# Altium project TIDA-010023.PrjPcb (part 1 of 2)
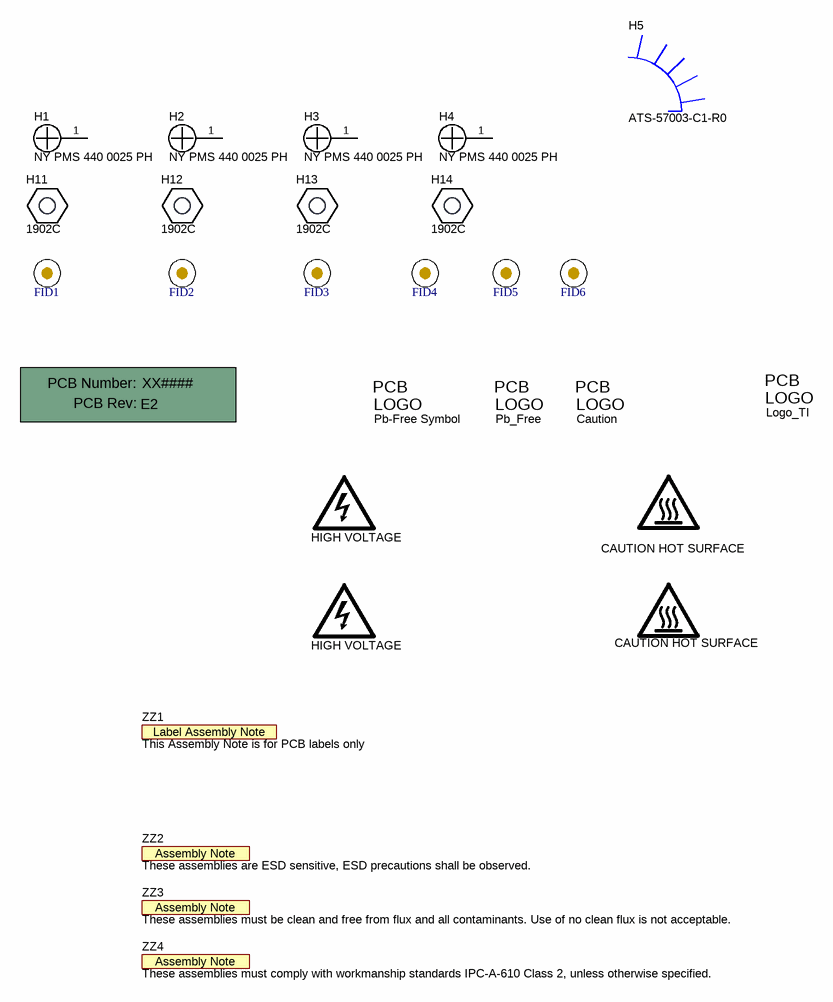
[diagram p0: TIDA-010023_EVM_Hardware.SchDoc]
CopyrightYear: 2017; PCB_Layout: Who did the Layout?; PCB_Rev: E1; PRJ_Customer: Public Release; PRJ_Engineer: Enter name of project lead; PRJ_Number: XX####; PRJ_Title: Change in menu Project|Project Options|Parameters; SCH_Rev: E1; TechSupport: http://www.ti.com/support; TID: N/A
5 sheets, 264 parts. Net scope: flat (ports and power ports of the same name join across sheets).
Board file: TIDA-010023_PCB.PcbDoc
Sheets:
  TIDA-010023_EVM_Hardware.SchDoc
  TIDA-010023_Current_Sensing.SchDoc
  TIDA-010023_Inverter.SchDoc
  TIDA-010023_MCU.SchDoc
  TIDA-010023_CoverSheet.SchDoc

## Sheet TIDA-010023_EVM_Hardware.SchDoc
size 431 x 279 mm; Date: Not shown in title block; ApprovedBy: Not shown in title block; CheckedBy: Not shown in title block; Author: Not shown in title block; CompanyName: Not shown in title block; Engineer: Not shown in title block; Organization: Not shown in title block; Address1: Not shown in title block; Address2: Not shown in title block; Address3: Not shown in title block; Address4: Not shown in title block; DocumentNumber: 1; Revision: Use project parameter SCH_Rev; SheetNumber: 3; SheetTotal: 3; PageSetup: Record=PageOptions¦CenterHorizontal=True¦CenterVertical=True¦PrintScale=1.00¦XCorrection=1.00¦YCorrection=1.00¦PrintKind=0¦BorderSize=5000000¦LeftOffset=0¦BottomOffset=0¦Orientation=2¦PaperLength=1000¦PaperWidth=1000¦Scale=100¦PaperSource=15¦PrintQuality=600¦MediaType=1¦DitherType=10¦PaperKind=Letter¦PrintScaleMode=1

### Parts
3  CAUTION HOT SURFACE  [IEC_HotSurface_small]  (no BOM)
4  CAUTION HOT SURFACE  [IEC_HotSurface_small]  (no BOM)
5  HIGH VOLTAGE  [IEC_HighVoltage_small]  (no BOM)
6  HIGH VOLTAGE  [IEC_HighVoltage_small]  (no BOM)
Caution  CAUTION.  READ USER GUIDE BEFORE USE  [IEC_Caution_small]  (value not drawn)  (no BOM)
FID1  Fiducial  [Fiducial10-30]  (value not drawn)
FID2  Fiducial  [Fiducial10-30]  (value not drawn)
FID3  Fiducial  [Fiducial10-30]  (value not drawn)
FID4  Fiducial  [Fiducial10-30]  (value not drawn)
FID5  Fiducial  [Fiducial10-30]  (value not drawn)
FID6  Fiducial  [Fiducial10-30]  (value not drawn)
H1  NY PMS 440 0025 PH  [NY PMS 440 0025 PH]
H2  NY PMS 440 0025 PH  [NY PMS 440 0025 PH]
H3  NY PMS 440 0025 PH  [NY PMS 440 0025 PH]
H4  NY PMS 440 0025 PH  [NY PMS 440 0025 PH]
H5  ATS-57003-C1-R0  [FE_LAM_5_K_100]  (mechanical)
H11  1902C  [Keystone_1902C]
H12  1902C  [Keystone_1902C]
H13  1902C  [Keystone_1902C]
H14  1902C  [Keystone_1902C]
LBL1  Printed Circuit Board  [Label_650x200]  (value not drawn)  (mechanical)
Logo_TI  Texas Instruments  [TI_Horizontal_Overlay_Small]  (value not drawn)  (no BOM)
Pb  Pb-Free Symbol  [Pb-Free_Overlay_Small]  (no BOM)
Pb_Free  ESD Susceptible  [ESD_Overlay_small]  (value not drawn)  (no BOM)
ZZ1  This Assembly Note is for PCB labels only  [AssemblyNoteLabel]  (no BOM)
ZZ2  These assemblies are ESD sensitive, ESD precautions shall be observed.  [AssemblyNote]  (no BOM)
ZZ3  These assemblies must be clean and free from flux and all contaminants. Use of no clean flux is not acceptable.  [AssemblyNote]  (no BOM)
ZZ4  These assemblies must comply with workmanship standards IPC-A-610 Class 2, unless otherwise specified.  [AssemblyNote]  (no BOM)

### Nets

Not connected (* = marked no-connect by the designer): H1 1; H2 1; H3 1; H4 1

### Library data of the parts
3 4 = IEC_HotSurface: IEC 61010-1 Hot Surface Warning; SymbolCreator: a0412235
5 6 = IEC_HighVoltage: IEC 61010-1 High Voltage Warning; SymbolCreator: a0412235
Caution = IEC_Caution: IEC 61010-1 Caution Warning; SymbolCreator: a0412235
FID1-FID6 = Fiducial: Fiducial mark.  There is nothing to buy or mount.; SymbolCreator: codlsc
H1-H4 = NY PMS 440 0025 PH: Machine Screw, Round, #4-40 x 1/4, Nylon, Philips panhead; Manufacturer: B&F Fastener Supply; CompType: Hardware; SymbolCreator: codlsc; U/M: EA
H5 = LAM 5 K 100: HEAT SINK 94MM X 94MM X 27MM; Manufacturer: Advanced Thermal Solutions Inc.; SymbolCreator: a0412235
H11-H14 = 1902C: Standoff, Hex, 0.5"L #4-40 Nylon; Manufacturer: Keystone; CompType: Hardware
LBL1 = PCB: Manufacturer: Any; PartNumber: XX####; SymbolCreator: a0412235
Logo_TI = TI_Logo: Texas Instrument Corporate Signature; SymbolCreator: a0412235
Pb = Pb-Free: SymbolCreator: a0412235
Pb_Free = ESD_Susceptible: ESD Susceptible Symbol; SymbolCreator: a0412235
ZZ1 = AssemblyNoteLabel: SymbolCreator: a0412235
ZZ2-ZZ4 = AssemblyNote: SymbolCreator: codlsc

## Sheet TIDA-010023_Current_Sensing.SchDoc
size 431 x 279 mm; Date: Not shown in title block; ApprovedBy: Not shown in title block; CheckedBy: Not shown in title block; Author: Not shown in title block; CompanyName: Not shown in title block; Engineer: Not shown in title block; Organization: Not shown in title block; Address1: Not shown in title block; Address2: Not shown in title block; Address3: Not shown in title block; Address4: Not shown in title block; DocumentNumber: 1; Revision: Use project parameter SCH_Rev; SheetNumber: 2; SheetTotal: 3; PageSetup: Record=PageOptions¦CenterHorizontal=True¦CenterVertical=True¦PrintScale=1.00¦XCorrection=1.00¦YCorrection=1.00¦PrintKind=0¦BorderSize=5000000¦LeftOffset=0¦BottomOffset=0¦Orientation=2¦PaperLength=1000¦PaperWidth=1000¦Scale=100¦PaperSource=15¦PrintQuality=600¦MediaType=1¦DitherType=10¦PaperKind=Letter¦PrintScaleMode=1
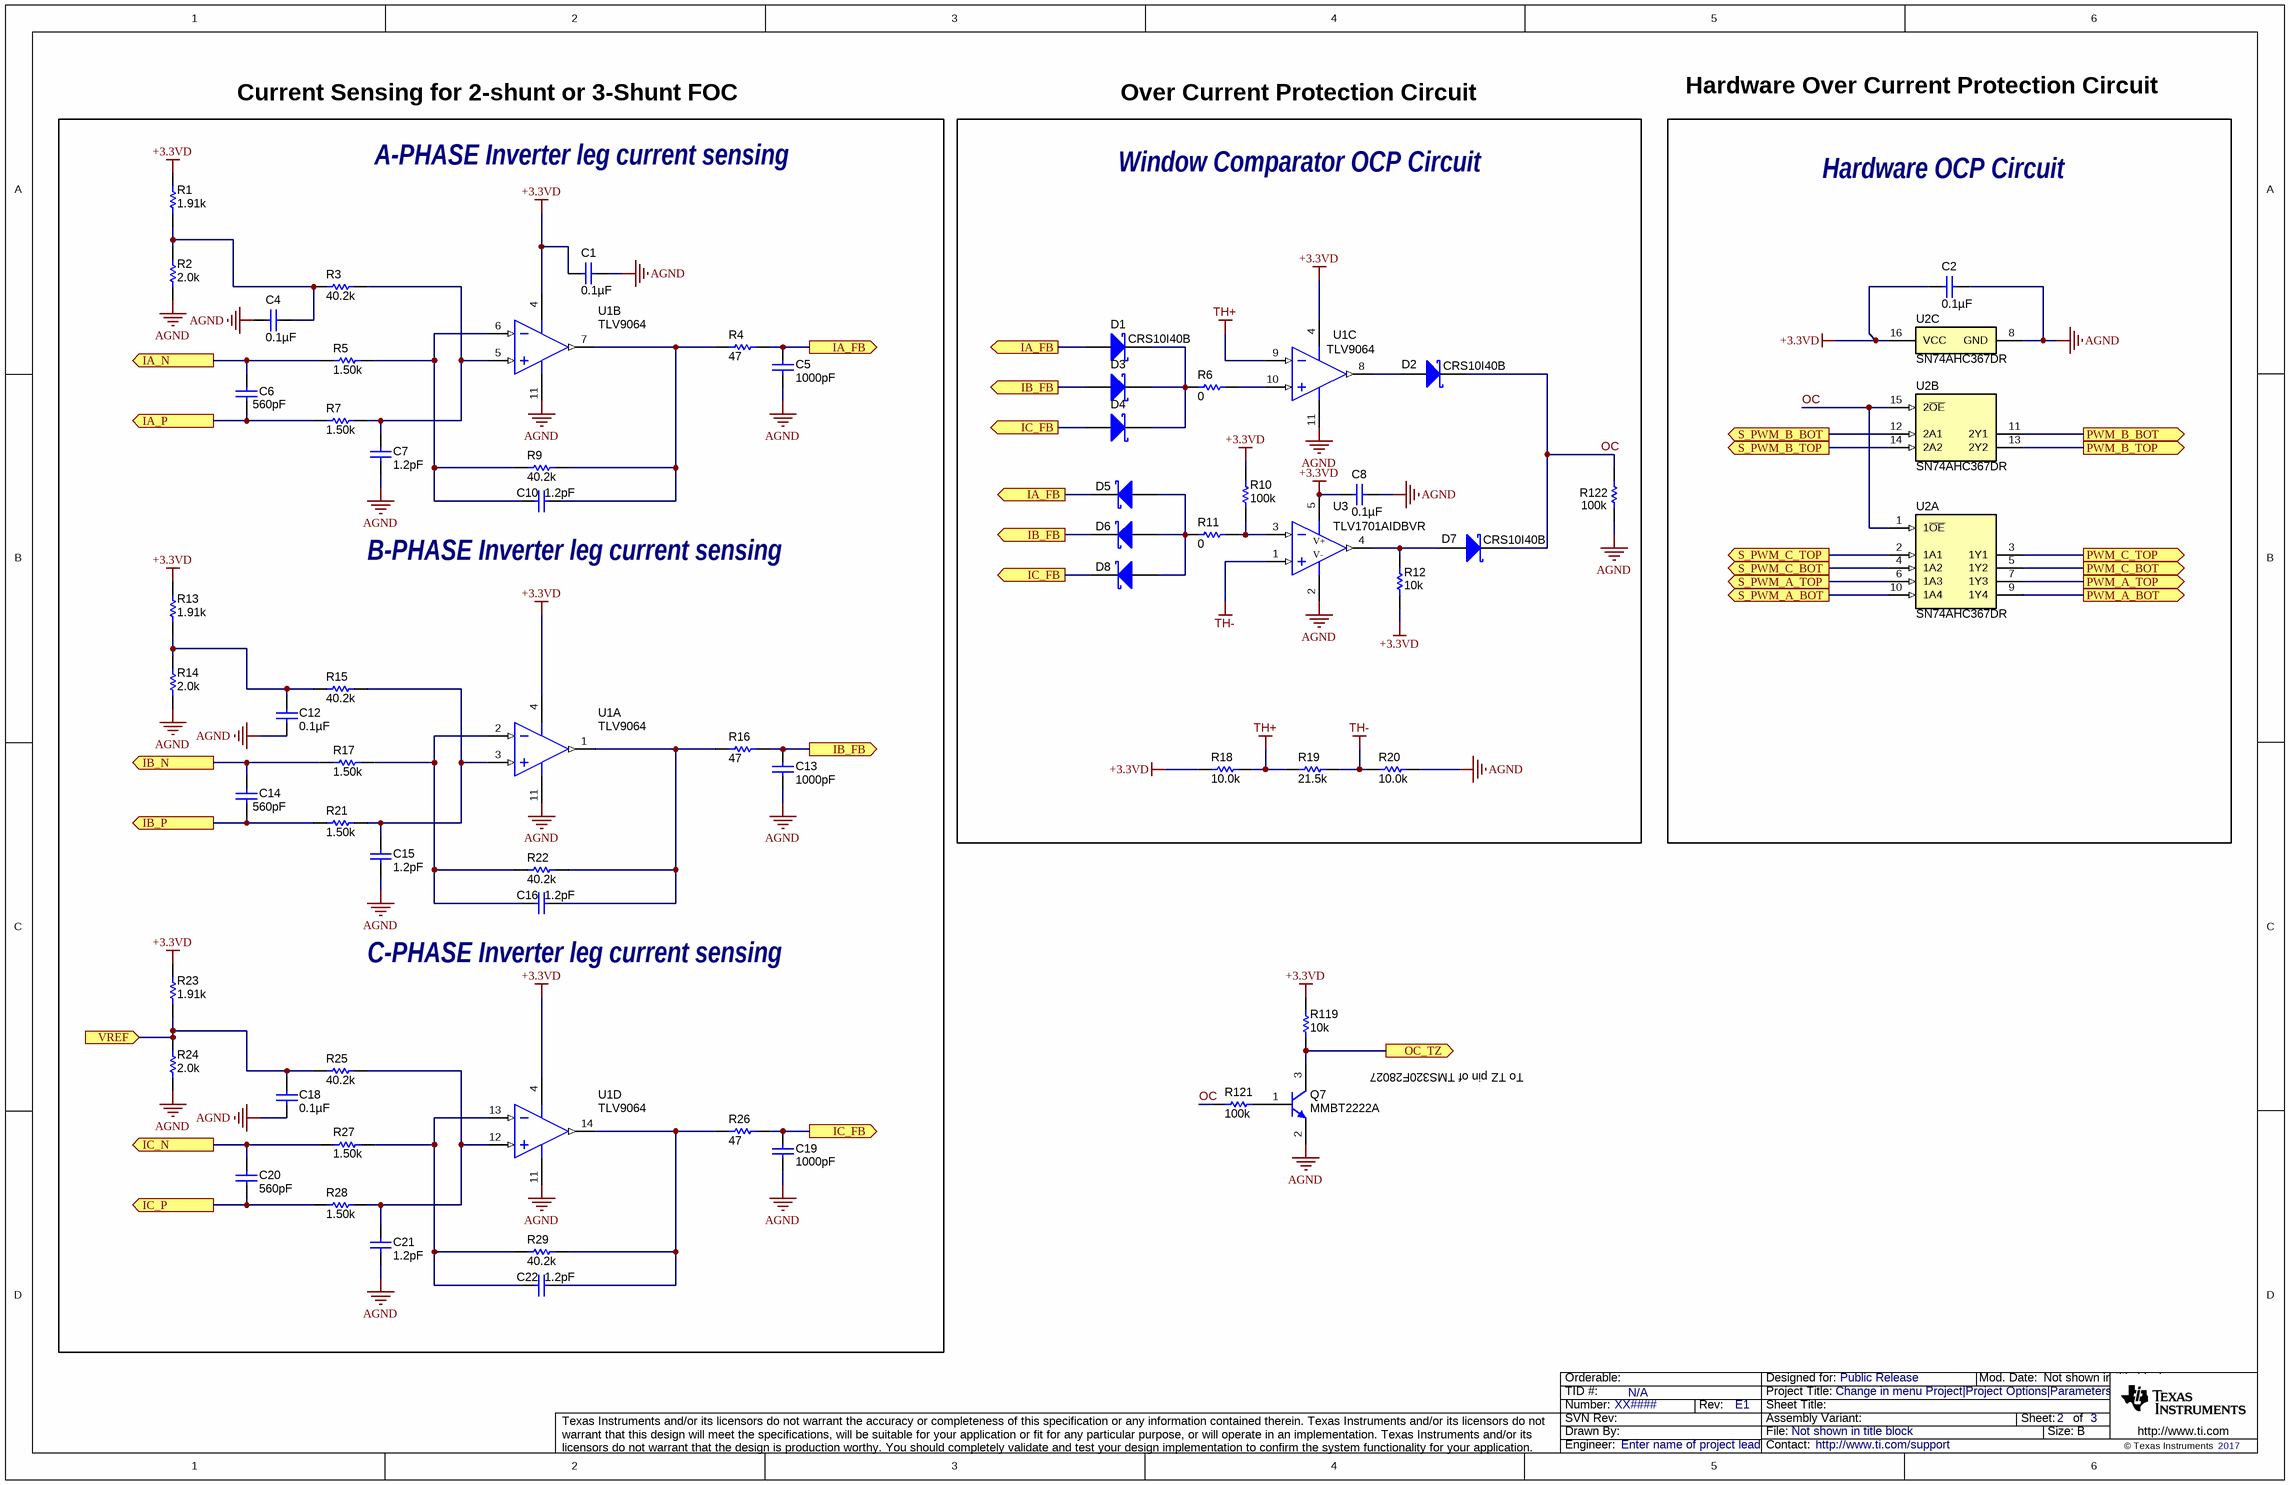
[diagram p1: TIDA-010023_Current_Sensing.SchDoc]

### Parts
C1  ValueDisplayed: 0.1µF  [0603]  (hidden comment: 0603YC104JAT2A)
C2  ValueDisplayed: 0.1µF  [0603]  (hidden comment: 0603YC104JAT2A)
C4  ValueDisplayed: 0.1µF  [0603]  (hidden comment: 0603YC104JAT2A)
C5  ValueDisplayed: 1000pF  [0603]  (hidden comment: 0603ZC102KAT2A)
C6  ValueDisplayed: 560pF  [0603]  (hidden comment: GRM1885C1E561JA01D)
C7  ValueDisplayed: 1.2pF  [0603]  (hidden comment: CL10C1R2BB8NNNC)
C8  ValueDisplayed: 0.1µF  [0603]  (hidden comment: 0603YC104JAT2A)
C10  ValueDisplayed: 1.2pF  [0603]  (hidden comment: CL10C1R2BB8NNNC)
C12  ValueDisplayed: 0.1µF  [0603]  (hidden comment: 0603YC104JAT2A)
C13  ValueDisplayed: 1000pF  [0603]  (hidden comment: 06035A221FAT2A)
C14  ValueDisplayed: 560pF  [0603]  (hidden comment: GRM1885C1E561JA01D)
C15  ValueDisplayed: 1.2pF  [0603]  (hidden comment: CL10C1R2BB8NNNC)
C16  ValueDisplayed: 1.2pF  [0603]  (hidden comment: CL10C1R2BB8NNNC)
C18  ValueDisplayed: 0.1µF  [0603]  (hidden comment: 0603YC104JAT2A)
C19  ValueDisplayed: 1000pF  [0603]  (hidden comment: 06035A221FAT2A)
C20  ValueDisplayed: 560pF  [0603]  (hidden comment: GRM1885C1E561JA01D)
C21  ValueDisplayed: 1.2pF  [0603]  (hidden comment: CL10C1R2BB8NNNC)
C22  ValueDisplayed: 1.2pF  [0603]  (hidden comment: CL10C1R2BB8NNNC)
D1  CRS10I40B  [SOD-123]
D2  CRS10I40B  [SOD-123]
D3  1N5819HW-7-F  [SOD-123]  (value not drawn)
D4  1N5819HW-7-F  [SOD-123]  (value not drawn)
D5  1N5819HW-7-F  [SOD-123]  (value not drawn)
D6  1N5819HW-7-F  [SOD-123]  (value not drawn)
D7  CRS10I40B  [SOD-123]
D8  1N5819HW-7-F  [SOD-123]  (value not drawn)
Q7  MMBT2222A  [SOT-23]
R1  ValueDisplayed: 1.91k  [0603]  (hidden comment: CRCW06031K91FKEA)
R2  ValueDisplayed: 2.0k  [0603]  (hidden comment: CRCW06032K00JNEA)
R3  ValueDisplayed: 40.2k  [0603]  (hidden comment: CRCW060340K2FKEA)
R4  ValueDisplayed: 47  [0603]  (hidden comment: CRCW060347R0JNEA)
R5  ValueDisplayed: 1.50k  [0603]  (hidden comment: CRCW06031K50FKEA)
R6  ValueDisplayed: 0  [0603]  (hidden comment: MCR03EZPJ000)
R7  ValueDisplayed: 1.50k  [0603]  (hidden comment: CRCW06031K50FKEA)
R9  ValueDisplayed: 40.2k  [0603]  (hidden comment: CRCW060340K2FKEA)
R10  ValueDisplayed: 100k  [0603]  (hidden comment: CRCW0603100KJNEA)
R11  ValueDisplayed: 0  [0603]  (hidden comment: MCR03EZPJ000)
R12  ValueDisplayed: 10k  [0603]  (hidden comment: CRCW060310K0JNEA)
R13  ValueDisplayed: 1.91k  [0603]  (hidden comment: CRCW06031K91FKEA)
R14  ValueDisplayed: 2.0k  [0603]  (hidden comment: CRCW06032K00JNEA)
R15  ValueDisplayed: 40.2k  [0603]  (hidden comment: CRCW060340K2FKEA)
R16  ValueDisplayed: 47  [0603]  (hidden comment: CRCW060347R0JNEA)
R17  ValueDisplayed: 1.50k  [0603]  (hidden comment: CRCW06031K50FKEA)
R18  ValueDisplayed: 10.0k  [0603]  (hidden comment: CRCW060310K0FKEA)
R19  ValueDisplayed: 21.5k  [0603]  (hidden comment: CRCW060321K5FKEA)
R20  ValueDisplayed: 10.0k  [0603]  (hidden comment: CRCW060310K0FKEA)
R21  ValueDisplayed: 1.50k  [0603]  (hidden comment: CRCW06031K50FKEA)
R22  ValueDisplayed: 40.2k  [0603]  (hidden comment: CRCW060340K2FKEA)
R23  ValueDisplayed: 1.91k  [0603]  (hidden comment: CRCW06031K91FKEA)
R24  ValueDisplayed: 2.0k  [0603]  (hidden comment: CRCW06032K00JNEA)
R25  ValueDisplayed: 40.2k  [0603]  (hidden comment: CRCW060340K2FKEA)
R26  ValueDisplayed: 47  [0603]  (hidden comment: CRCW060347R0JNEA)
R27  ValueDisplayed: 1.50k  [0603]  (hidden comment: CRCW06031K50FKEA)
R28  ValueDisplayed: 1.50k  [0603]  (hidden comment: CRCW06031K50FKEA)
R29  ValueDisplayed: 40.2k  [0603]  (hidden comment: CRCW060340K2FKEA)
R119  ValueDisplayed: 10k  [0603]  (hidden comment: CRCW060310K0JNEA)
R121  ValueDisplayed: 100k  [0603]  (hidden comment: CRCW0603100KJNEA)
R122  ValueDisplayed: 100k  [0603]  (hidden comment: CRCW0603100KJNEA)
U1  TLV9064  [tssop-14]  (parts A,B,C,D of 4)
U2  SN74AHC367DR  [D0016A_N]  (parts A,B,C of 3)
U3  TLV1701AIDBVR  [DBV0005A_N]

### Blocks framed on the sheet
Window Comparator OCP Circuit: C8 D1-D8 R6 R10-R12 R18-R20 R122 U1 U3
Hardware OCP Circuit: C2 U2

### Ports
IA_FB (out), IA_N (out), IA_P (out), IB_FB (out), IB_N (out), IB_P (out), IC_FB (out), IC_N (out), IC_P (out), OC_TZ (out), PWM_A_BOT (out), PWM_A_TOP (out), PWM_B_BOT (out), PWM_B_TOP (out), PWM_C_BOT (out), PWM_C_TOP (out), S_PWM_A_BOT (out), S_PWM_A_TOP (out), S_PWM_B_BOT (out), S_PWM_B_TOP (out), S_PWM_C_BOT (out), S_PWM_C_TOP (out), VREF (in)

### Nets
+3.3VD: C1.1 C2.2 C8.1 R1.2 R10.1 R12.2 R13.2 R18.2 R23.2 R119.1 U1.4(VDD) U2.16(VCC) U3.5(V+)
AGND: C1.2 C2.1 C4.1 C5.2 C7.2 C8.2 C12.2 C13.2 C15.2 C18.2 C19.2 C21.2 Q7.2(E) R2.1 R14.1 R20.1 R24.1 R122.1 U1.11(GND) U2.8(GND) U3.2(V-)
TH+: R18.1 R19.2 U1.9(IN3-)
TH-: R19.1 R20.2 U3.1(IN+)
IA_FB: C5.1 D1.2(A) D5.1(K) R4.2 ; port IA_FB
IA_N: C6.1 R5.1 ; port IA_N
IA_P: C6.2 R7.1 ; port IA_P
IB_FB: C13.1 D3.2(A) D6.1(K) R16.2 ; port IB_FB
IB_N: C14.1 R17.1 ; port IB_N
IB_P: C14.2 R21.1 ; port IB_P
IC_FB: C19.1 D4.2(A) D8.1(K) R26.2 ; port IC_FB
IC_N: C20.2 R27.1 ; port IC_N
IC_P: C20.1 R28.1 ; port IC_P
OC: D2.1(K) D7.1(K) R121.1 R122.2 U2.1(1~{OE}) U2.15(2~{OE})
OC_TZ: Q7.3(C) R119.2 ; port OC_TZ
PWM_A_BOT: U2.9(1Y4) ; port PWM_A_BOT
PWM_A_TOP: U2.7(1Y3) ; port PWM_A_TOP
PWM_B_BOT: U2.11(2Y1) ; port PWM_B_BOT
PWM_B_TOP: U2.13(2Y2) ; port PWM_B_TOP
PWM_C_BOT: U2.5(1Y2) ; port PWM_C_BOT
PWM_C_TOP: U2.3(1Y1) ; port PWM_C_TOP
S_PWM_A_BOT: U2.10(1A4) ; port S_PWM_A_BOT
S_PWM_A_TOP: U2.6(1A3) ; port S_PWM_A_TOP
S_PWM_B_BOT: U2.12(2A1) ; port S_PWM_B_BOT
S_PWM_B_TOP: U2.14(2A2) ; port S_PWM_B_TOP
S_PWM_C_BOT: U2.4(1A2) ; port S_PWM_C_BOT
S_PWM_C_TOP: U2.2(1A1) ; port S_PWM_C_TOP
VREF: C18.1 R23.1 R24.2 R25.1 ; port VREF
NetC4_2: C4.2 R1.1 R2.2 R3.1
NetC7_1: C7.1 R3.2 R7.2 U1.5(IN2+)
NetC10_1: C10.1 R4.1 R9.2 U1.7(OUT2)
NetC10_2: C10.2 R5.2 R9.1 U1.6(IN2-)
NetC12_1: C12.1 R13.1 R14.2 R15.1
NetC15_1: C15.1 R15.2 R21.2 U1.3(IN1+)
NetC16_1: C16.1 R16.1 R22.2 U1.1(OUT1)
NetC16_2: C16.2 R17.2 R22.1 U1.2(IN1-)
NetC21_1: C21.1 R25.2 R28.2 U1.12(IN4+)
NetC22_1: C22.1 R26.1 R29.2 U1.14(OUT4)
NetC22_2: C22.2 R27.2 R29.1 U1.13(IN4-)
NetD1_1: D1.1(K) D3.1(K) D4.1(K) R6.2
NetD2_2: D2.2(A) U1.8(OUT3)
NetD5_2: D5.2(A) D6.2(A) D8.2(A) R11.2
NetD7_2: D7.2(A) R12.1 U3.4(OUT)
NetQ7_1: Q7.1(B) R121.2
NetR6_1: R6.1 U1.10(IN3+)
NetR10_2: R10.2 R11.1 U3.3(IN-)

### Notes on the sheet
- Current Sensing for 2-shunt or 3-Shunt FOC
- Over Current Protection Circuit
- Hardware Over Current Protection Circuit
- A-PHASE Inverter leg current sensing
- (near C10) B-PHASE Inverter leg current sensing
- (near C16) C-PHASE Inverter leg current sensing
- To TZ pin of TMS320F28027

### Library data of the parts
C1 C4 C12 C18 = 0603YC104JAT2A: CAP, CERM, 0.1 µF, 16 V, +/- 5%, X7R, 0603; Manufacturer: AVX; Polarized: N; CompType: Capacitor; Value: 0.1uF; U/M: EA; Cap_F: 0.0000001; Tolerance_%: 5; ESR_ohm: 0.039; Value1: 0.039 ohm; VDC_V: 16; Value2: 16V; TaMin_C: -55; TaMax_C: 125; SizeArea_mm2: 1.28; SizeAreaWB_mm2: 4.68; SizeX_mm: 1.6; SizeY_mm: 0.8; SizeZ_mm: 1; AEC Category: Q200
C2 C8 = 0603YC104JAT2A: CAP, CERM, 0.1 µF, 16 V, +/- 5%, X7R, 0603; Manufacturer: AVX; Polarized: N; CompType: Capacitor; Value: 0.1uF; U/M: EA; Cap_F: 0.0000001; Tolerance_%: 5; ESR_ohm: 0.039; Value1: 0.039 ohm; VDC_V: 16; Value2: 16V; TaMin_C: -55; TaMax_C: 125
C5 = 0603ZC102KAT2A: CAP, CERM, 1000 pF, 10 V,+/- 10%, X7R, 0603; Manufacturer: AVX; Polarized: N; CompType: Capacitor; Value: 1000pF; U/M: EA; Cap_F: 0.000000001; Tolerance_%: 10; Value2: 10V; TaMin_C: -55; TaMax_C: 125; SizeArea_mm2: 1.28; SizeAreaWB_mm2: 4.68; SizeX_mm: 1.6; SizeY_mm: 0.8; SizeZ_mm: 1; AEC Category: Q200
C6 C14 C20 = GRM1885C1E561JA01D: CAP, CERM, 560 pF, 25 V,+/- 5%, C0G/NP0, 0603; Manufacturer: MuRata; Polarized: N; CompType: Capacitor; Value: 560pF; U/M: EA; Cap_F: 0.00000000056; Tolerance_%: 5; VDC_V: 25; Value2: 25V; TaMin_C: -55; TaMax_C: 125; SizeArea_mm2: 1.28; SizeAreaWB_mm2: 4.68; SizeX_mm: 1.6; SizeY_mm: 0.8; SizeZ_mm: 1; AEC Category: Q200
C7 C10 C15 C16 C21 C22 = CL10C1R2BB8NNNC: CAP, CERM, 1.2 pF, 50 V,+/- 10%, C0G/NP0, 0603; Manufacturer: Samsung Electro-Mechanics; Polarized: N; CompType: Capacitor; Value: 1.2pF; U/M: EA; Cap_F: 0.0000000000012; Tolerance_%: 10; VDC_V: 50; Value2: 50V; TaMin_C: -55; TaMax_C: 125; SizeArea_mm2: 1.28; SizeAreaWB_mm2: 4.68; SizeX_mm: 1.6; SizeY_mm: 0.8; SizeZ_mm: 1; AEC Category: Q200
C13 C19 = 06035A221FAT2A: CAP, CERM, 220 pF, 50 V, +/- 1%, C0G/NP0, 0603; Manufacturer: AVX; Polarized: N; CompType: Capacitor; Value: 220pF; U/M: EA; Cap_F: 0.00000000022; Tolerance_%: 1; ESR_ohm: 0.083; Value1: 0.083 ohm; VDC_V: 50; Value2: 50V; TaMin_C: -55; TaMax_C: 125
D1-D8 = 1N5819HW-7-F: Diode, Schottky, 40V, 1A, SOD-123; Manufacturer: Diodes Inc.; U/M: EA; Vf_V: 0.45; Value2: 0.45V; Io_A: 1; Vr_V: 40; TJmax_C: 125
Q7 = MMBT2222A, Fairchild Semiconductor: Transistor, NPN, 40 V, 0.15 A, SOT-23; CompType: BJT; PNP: 0; NPN: 1; Vceo_V: 40; Vcesat1_V: 0.3; Value: 40 V; IcRated_A: 0.15; Value1: 0.15 A; HfeMax: 300; TaMin_C: -55; TaMax_C: 150; SizeAreaWB_mm2: 14; SizeArea_mm2: 7.5; SizeX_mm: 2.5; SizeY_mm: 3; SizeZ_mm: 1.1; U/M: EA; AEC Category: Q101; Green_Lifecycle: Active; Green_REACh: Passed
R1 R13 R23 = CRCW06031K91FKEA: RES, 1.91 k, 1%, 0.1 W, 0603; Manufacturer: Vishay-Dale; CompType: Resistor; Value: 1.91k; Res_ohm: 1910; Value_Code: 1k91; Tolerance_%: 1; Power_W: 0.1; Value2: 0.1W; VDC_V: 75; TempCo: 100 ppm/C; SizeArea_mm2: 1.28; SizeX_mm: 1.6; SizeY_mm: 0.8; EIA_Code: E96; U/M: EA; AEC Category: Q200
R2 R14 R24 = CRCW06032K00JNEA: RES, 2.0 k, 5%, 0.1 W, 0603; Manufacturer: Vishay-Dale; CompType: Resistor; Value: 2.0k; Res_ohm: 2000; Value_Code: 2k00; Tolerance_%: 5; Power_W: 0.1; Value2: 0.1W; VDC_V: 75; TempCo: 200 ppm/C; SizeArea_mm2: 1.28; SizeX_mm: 1.6; SizeY_mm: 0.8; SizeZ_mm: 1; EIA_Code: E24; U/M: EA; AEC Category: Q200; Green_Lifecycle: Active; Green_REACh: Passed
R3 R9 R15 R22 R25 R29 = CRCW060340K2FKEA: RES, 40.2 k, 1%, 0.1 W, 0603; Manufacturer: Vishay-Dale; CompType: Resistor; Value: 40.2k; Res_ohm: 40200; Value_Code: 40k2; Tolerance_%: 1; Power_W: 0.1; Value2: 0.1W; VDC_V: 75; TempCo: 100 ppm/C; SizeArea_mm2: 1.28; SizeX_mm: 1.6; SizeY_mm: 0.8; EIA_Code: E96; U/M: EA; AEC Category: Q200; Green_Lifecycle: Active; Green_REACh: Passed
R4 R16 R26 = CRCW060347R0JNEA: RES, 47, 5%, 0.1 W, 0603; Manufacturer: Vishay-Dale; CompType: Resistor; Value: 47; Value_Code: 47R0; Tolerance_%: 5; Power_W: 0.1; Value2: 0.1W; VDC_V: 75; TempCo: 200 ppm/C; SizeArea_mm2: 1.28; SizeX_mm: 1.6; SizeY_mm: 0.8; SizeZ_mm: 1; EIA_Code: E24; U/M: EA; AEC Category: Q200; Green_Lifecycle: Active; Green_REACh: Passed
R5 R7 R17 R21 R27 R28 = CRCW06031K50FKEA: RES, 1.50 k, 1%, 0.1 W, 0603; Manufacturer: Vishay-Dale; CompType: Resistor; Value: 1.50k; Res_ohm: 1500; Value_Code: 1k50; Tolerance_%: 1; Power_W: 0.1; Value2: 0.1W; VDC_V: 75; TempCo: 100 ppm/C; SizeArea_mm2: 1.28; SizeX_mm: 1.6; SizeY_mm: 0.8; EIA_Code: E96; U/M: EA; AEC Category: Q200; Green_Lifecycle: Active; Green_REACh: Passed
R6 R11 = MCR03EZPJ000: RES, 0, 5%, 0.1 W, 0603; Manufacturer: Rohm; CompType: Resistor; Value: 0; Value_Code: 0000; Tolerance_%: 5; Power_W: 0.1; Value2: 0.1W; VDC_V: 50; TempCo: 400 ppm/C; SizeArea_mm2: 1.28; SizeX_mm: 1.6; SizeY_mm: 0.8; SizeZ_mm: 1; EIA_Code: E24; U/M: EA; AEC Category: Q200; AEC Qualified: N; Green_Lifecycle: Active; Green_REACh: Passed
R10 R121 R122 = CRCW0603100KJNEA: RES, 100 k, 5%, 0.1 W, 0603; Manufacturer: Vishay-Dale; CompType: Resistor; Value: 100k; Res_ohm: 100000; Tolerance_%: 5; Power_W: 0.1; Value2: 0.1W; VDC_V: 75; TempCo: 200 ppm/C; SizeArea_mm2: 1.28; SizeX_mm: 1.6; SizeY_mm: 0.8; SizeZ_mm: 1; EIA_Code: E24; U/M: EA; AEC Category: Q200; Green_Lifecycle: Active; Green_REACh: Passed
R12 R119 = CRCW060310K0JNEA: RES, 10 k, 5%, 0.1 W, 0603; Manufacturer: Vishay-Dale; CompType: Resistor; Value: 10k; Res_ohm: 10000; Value_Code: 10k0; Tolerance_%: 5; Power_W: 0.1; Value2: 0.1W; VDC_V: 75; TempCo: 200 ppm/C; SizeArea_mm2: 1.28; SizeX_mm: 1.6; SizeY_mm: 0.8; SizeZ_mm: 1; EIA_Code: E24; U/M: EA; AEC Category: Q200; Green_Lifecycle: Active; Green_REACh: Passed
R18 R20 = CRCW060310K0FKEA: RES, 10.0 k, 1%, 0.1 W, 0603; Manufacturer: Vishay-Dale; CompType: Resistor; Value: 10.0k; Res_ohm: 10000; Value_Code: 10k0; Tolerance_%: 1; Power_W: 0.1; Value2: 0.1W; VDC_V: 75; TempCo: 100 ppm/C; EIA_Code: E96; U/M: EA; SizeArea_mm2: 1.28; SizeX_mm: 1.6; SizeY_mm: 0.8; AEC Category: Q200
R19 = CRCW060321K5FKEA: RES, 21.5 k, 1%, 0.1 W, 0603; Manufacturer: Vishay-Dale; CompType: Resistor; Value: 21.5k; Res_ohm: 21500; Value_Code: 21k5; Tolerance_%: 1; Power_W: 0.1; Value2: 0.1W; VDC_V: 75; TempCo: 100 ppm/C; SizeArea_mm2: 1.28; SizeX_mm: 1.6; SizeY_mm: 0.8; EIA_Code: E96; U/M: EA; AEC Category: Q200
U1 = TLV2774AID: Quad High-Slew-Rate Rail-to-Rail Output Operational Amplifier, 2.5 to 6 V, -40 to 125 degC, 14-pin SOIC (D0014A), Green (RoHS & no Sb/Br); Manufacturer: Texas Instruments; Alternate PartNumber: Equivalent; PartNumber: TLV2774AIDA; CMRR(Min)(dB): 70; GBW(Typ)(MHz): 5.1; IIB(Max)(pA): 60; Iq per channel(Max)(mA): 2; Number of Channels: 4; Packing: TUBE; Rating: Catalog; Slew Rate(Typ)(V/us): 10.5; Sub Family: Low Supply Voltage Amplifier (<=2.7V), Precision Amplifier; Total Supply Voltage(Max)(+5V is 5, +/-5V is 10): 6; Total Supply Voltage(Min)(+5V is 5, +/-5V is 10): 2.5; Vio (25C)(Max)(mV): 2.1
U2 = SN74AHC367DR: Hex Buffers And Line Drivers With 3-State Outputs, D0016A, LARGE T&R; Manufacturer: Texas Instruments; Alternate PartNumber: Equivalent; VCC(Min)(V): 2; VCC(Max)(V): 5.5; Output Type: CMOS; ICC @ Nom Voltage(Max)(mA): 0.04; Bits(#): 6; F @ Nom Voltage(Max)(Mhz): 110; Rating: Catalog; Voltage(Nom)(V): 3.3,5; tpd @ Nom Voltage(Max)(ns): 12.5,8.5
U3 = TLV1701AIDBVR: 2.2-V to 36-V, microPower Comparator, DBV0005A; Alternate PartNumber: TLV1701AIDBVT; Manufacturer: Texas Instruments; SizeArea_mm2: 8.12; SizeAreaWB_mm2: 14.82; SizeX_mm: 2.8; SizeY_mm: 2.9; SizeZ_mm: 1.45; CompType: IC; U/M: EA; Sim Note: Shutdown not modeled

## Sheet TIDA-010023_Inverter.SchDoc
size 431 x 279 mm; Date: Not shown in title block; ApprovedBy: Not shown in title block; CheckedBy: Not shown in title block; Author: Not shown in title block; CompanyName: Not shown in title block; Engineer: Not shown in title block; Organization: Not shown in title block; Address1: Not shown in title block; Address2: Not shown in title block; Address3: Not shown in title block; Address4: Not shown in title block; DocumentNumber: 1; Revision: Use project parameter SCH_Rev; SheetNumber: 2; SheetTotal: 3; PageSetup: Record=PageOptions¦CenterHorizontal=True¦CenterVertical=True¦PrintScale=1.00¦XCorrection=1.00¦YCorrection=1.00¦PrintKind=0¦BorderSize=5000000¦LeftOffset=0¦BottomOffset=0¦Orientation=2¦PaperLength=1000¦PaperWidth=1000¦Scale=100¦PaperSource=15¦PrintQuality=600¦MediaType=1¦DitherType=10¦PaperKind=Letter¦PrintScaleMode=1
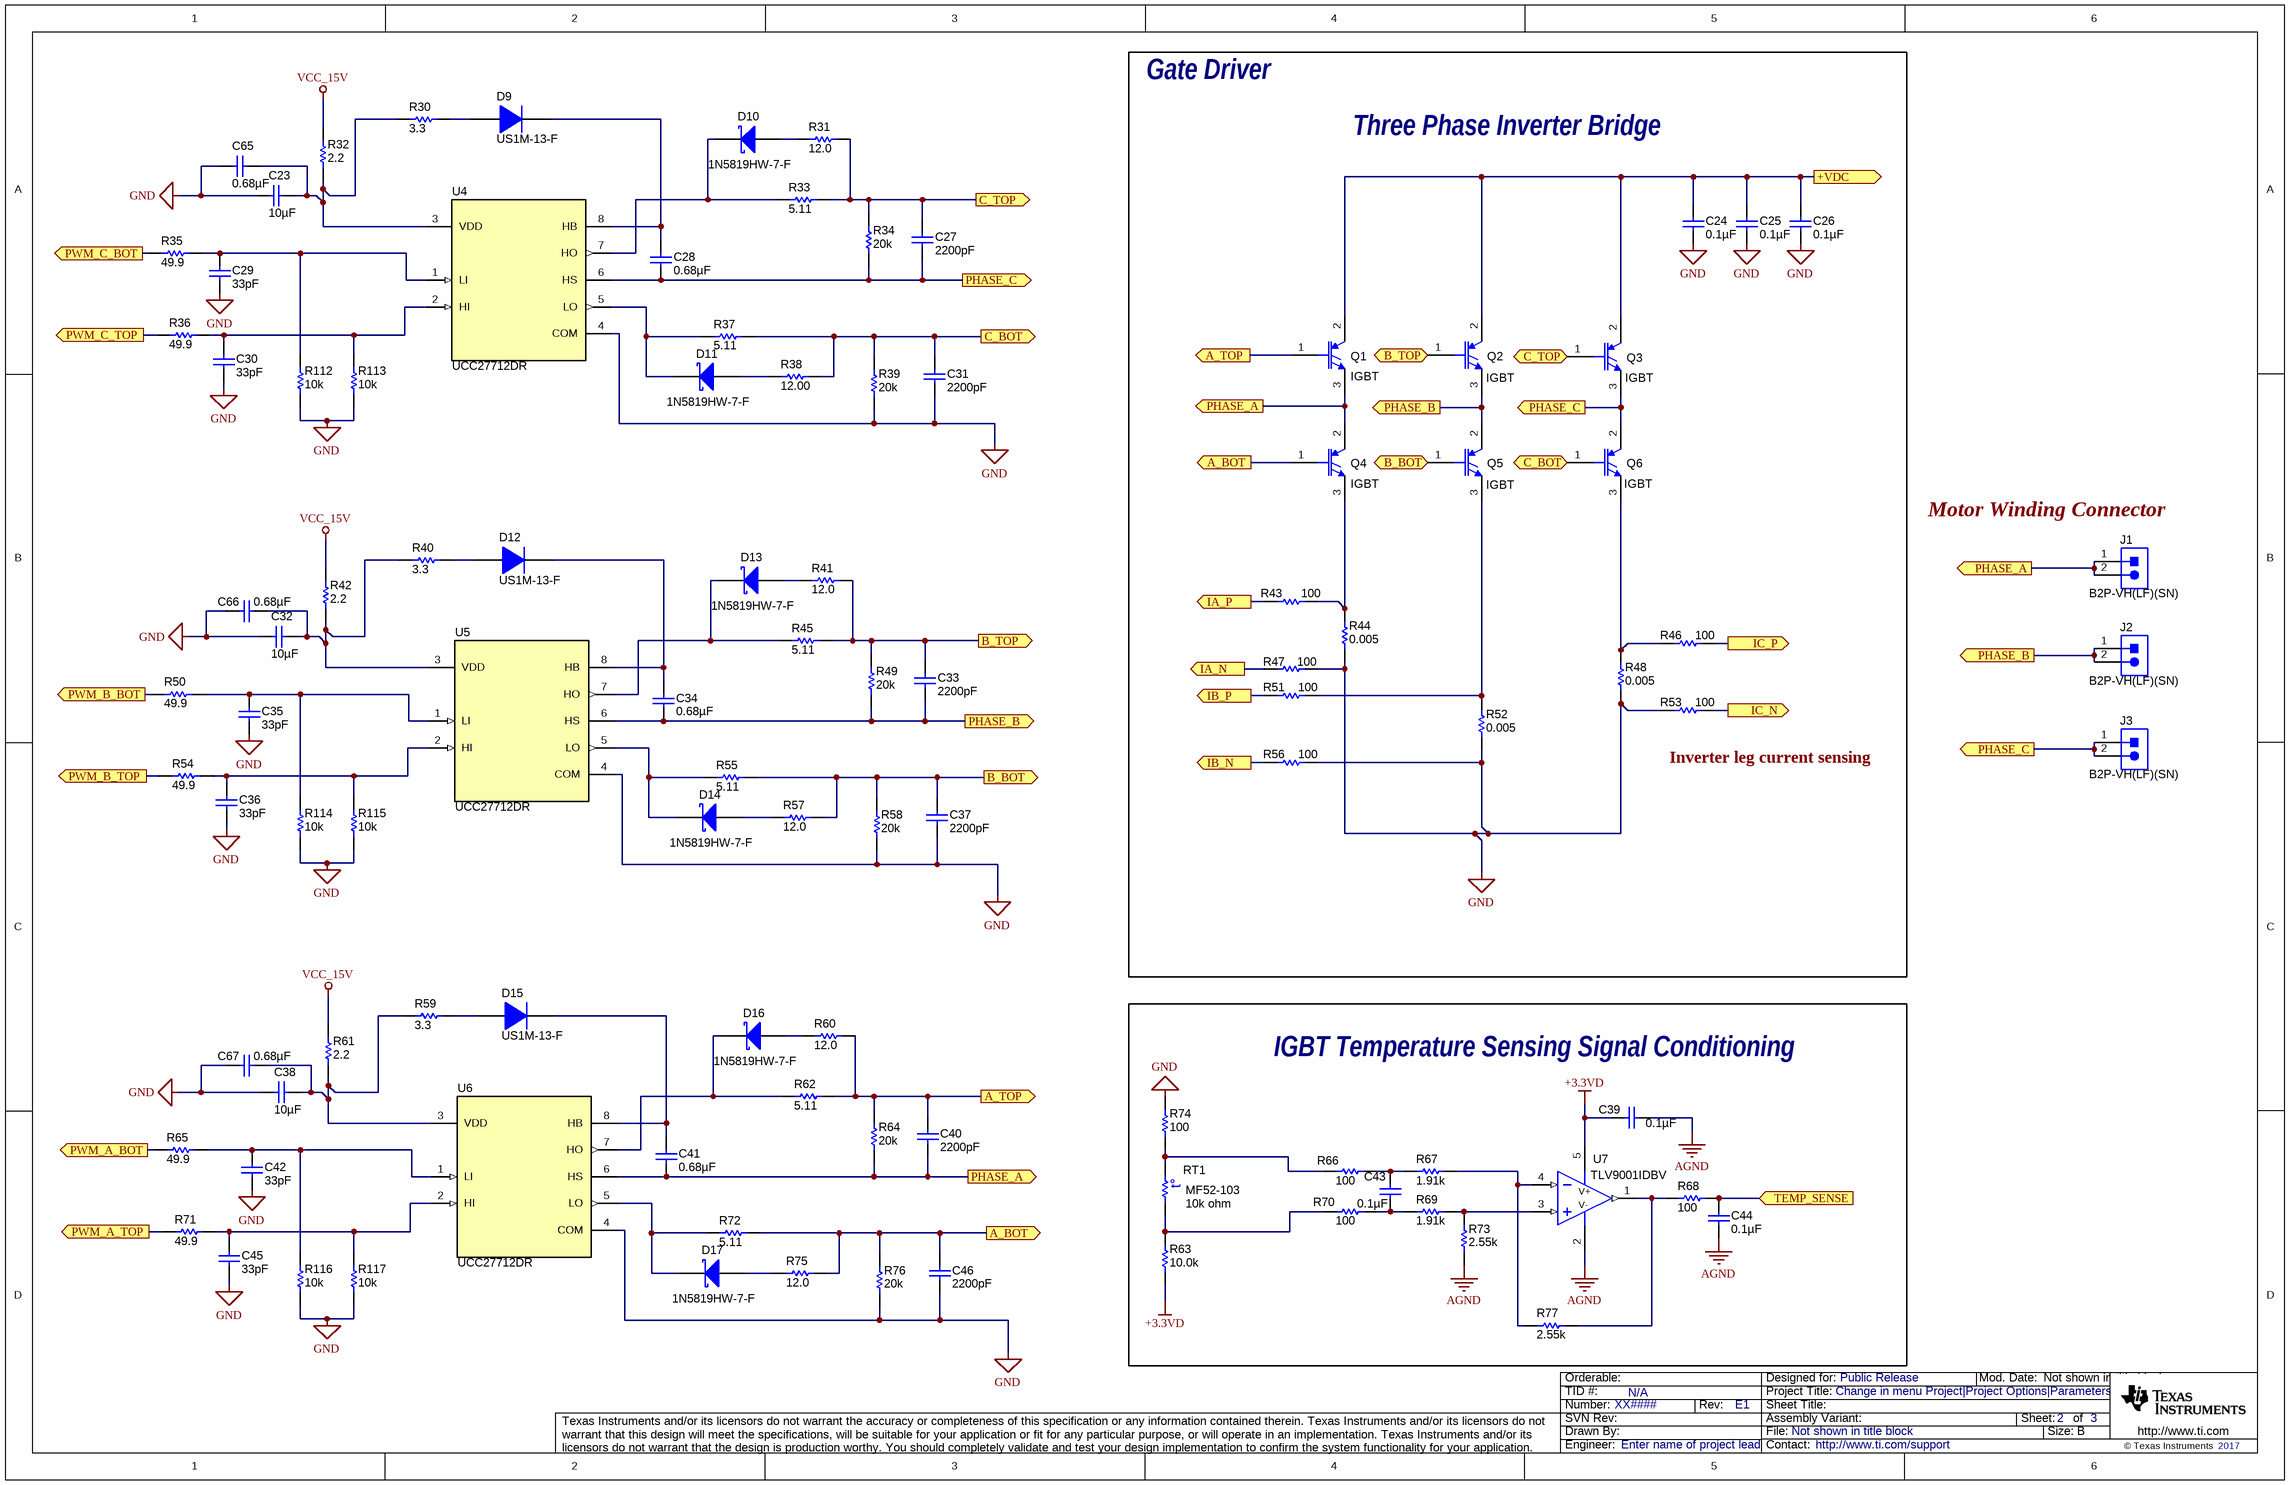
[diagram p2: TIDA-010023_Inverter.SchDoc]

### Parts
C23  ValueDisplayed: 10µF  [0805_HV]  (hidden comment: C2012X5R1E106K125AB)
C24  ValueDisplayed: 0.1µF  [1812_254]  (hidden comment: C1812V104KDRACTU)
C25  ValueDisplayed: 0.1µF  [1812_254]  (hidden comment: C1812V104KDRACTU)
C26  ValueDisplayed: 0.1µF  [1812_254]  (hidden comment: C1812V104KDRACTU)
C27  ValueDisplayed: 2200pF  [0603]  (hidden comment: GRM188R71E222KA01D)
C28  ValueDisplayed: 0.68µF  [0805_HV]  (hidden comment: C0805C105K3RACTU)
C29  ValueDisplayed: 33pF  [0603]  (hidden comment: 06035A221FAT2A)
C30  ValueDisplayed: 33pF  [0603]  (hidden comment: 06035A221FAT2A)
C31  ValueDisplayed: 2200pF  [0603]  (hidden comment: GRM188R71E222KA01D)
C32  ValueDisplayed: 10µF  [0805_HV]  (hidden comment: C2012X5R1E106K125AB)
C33  ValueDisplayed: 2200pF  [0603]  (hidden comment: GRM188R71E222KA01D)
C34  ValueDisplayed: 0.68µF  [0805_HV]  (hidden comment: C0805C105K3RACTU)
C35  ValueDisplayed: 33pF  [0603]  (hidden comment: 06035A221FAT2A)
C36  ValueDisplayed: 33pF  [0603]  (hidden comment: 06035A221FAT2A)
C37  ValueDisplayed: 2200pF  [0603]  (hidden comment: GRM188R71E222KA01D)
C38  ValueDisplayed: 10µF  [0805_HV]  (hidden comment: C2012X5R1E106K125AB)
C39  ValueDisplayed: 0.1µF  [0603]  (hidden comment: 0603YC104JAT2A)
C40  ValueDisplayed: 2200pF  [0603]  (hidden comment: GRM188R71E222KA01D)
C41  ValueDisplayed: 0.68µF  [0805_HV]  (hidden comment: C0805C105K3RACTU)
C42  ValueDisplayed: 33pF  [0603]  (hidden comment: 06035A221FAT2A)
C43  ValueDisplayed: 0.1µF  [0603]  (hidden comment: 0603YC104JAT2A)
C44  ValueDisplayed: 0.1µF  [0603]  (hidden comment: 0603YC104JAT2A)
C45  ValueDisplayed: 33pF  [0603]  (hidden comment: 06035A221FAT2A)
C46  ValueDisplayed: 2200pF  [0603]  (hidden comment: GRM188R71E222KA01D)
C65  ValueDisplayed: 0.68µF  [0805_HV]  (hidden comment: C0805C105K3RACTU)
C66  ValueDisplayed: 0.68µF  [0805_HV]  (hidden comment: C0805C105K3RACTU)
C67  ValueDisplayed: 0.68µF  [0805_HV]  (hidden comment: C0805C105K3RACTU)
D9  US1M-13-F  [SMA]
D10  1N5819HW-7-F  [SOD-123]
D11  1N5819HW-7-F  [SOD-123]
D12  US1M-13-F  [SMA]
D13  1N5819HW-7-F  [SOD-123]
D14  1N5819HW-7-F  [SOD-123]
D15  US1M-13-F  [SMA]
D16  1N5819HW-7-F  [SOD-123]
D17  1N5819HW-7-F  [SOD-123]
J1  B2P-VH(LF)(SN)  [6.3mm 2P PHASE]
J2  B2P-VH(LF)(SN)  [6.3mm 2P PHASE]
J3  B2P-VH(LF)(SN)  [6.3mm 2P PHASE]
Q1  IGBT  [TO-220AB_HORIZONTAL]
Q2  IGBT  [TO-220AB_HORIZONTAL]
Q3  IGBT  [TO-220AB_HORIZONTAL]
Q4  IGBT  [TO-220AB_HORIZONTAL]
Q5  IGBT  [TO-220AB_HORIZONTAL]
Q6  IGBT  [TO-220AB_HORIZONTAL]
R30  value 3.3  [1206]  (hidden comment: CRCW12063R30JNEA)
R31  ValueDisplayed: 12.0  [1206]  (hidden comment: RC1206FR-0712RL)
R32  ValueDisplayed: 2.2  [1206]  (hidden comment: RC0603FR-075R11L)
R33  ValueDisplayed: 5.11  [1206]  (hidden comment: CRCW12066R04FKEA)
R34  ValueDisplayed: 20k  [0603]  (hidden comment: CRCW060320K0FKEA)
R35  ValueDisplayed: 49.9  [0603]  (hidden comment: CRCW060351R1FKEA)
R36  ValueDisplayed: 49.9  [0603]  (hidden comment: CRCW060351R1FKEA)
R37  ValueDisplayed: 5.11  [1206]  (hidden comment: CRCW12066R04FKEA)
R38  ValueDisplayed: 12.00  [1206]  (hidden comment: RC1206FR-0712RL)
R39  ValueDisplayed: 20k  [0603]  (hidden comment: CRCW060320K0FKEA)
R40  value 3.3  [1206]  (hidden comment: CRCW12063R30JNEA)
R41  ValueDisplayed: 12.0  [1206]  (hidden comment: RC1206FR-0712RL)
R42  ValueDisplayed: 2.2  [1206]  (hidden comment: RC0603FR-075R11L)
R43  ValueDisplayed: 100  [0603]  (hidden comment: CRCW06030000Z0EA)
R44  ValueDisplayed: 0.005  [CRE2512-R5_R9]  (hidden comment: CRE2512-FZ-R005E-3)
R45  ValueDisplayed: 5.11  [1206]  (hidden comment: CRCW12066R04FKEA)
R46  ValueDisplayed: 100  [0603]  (hidden comment: CRCW06030000Z0EA)
R47  ValueDisplayed: 100  [0603]  (hidden comment: CRCW06030000Z0EA)
R48  ValueDisplayed: 0.005  [CRE2512-R5_R9]  (hidden comment: CRE2512-FZ-R005E-3)
R49  ValueDisplayed: 20k  [0603]  (hidden comment: CRCW060320K0FKEA)
R50  ValueDisplayed: 49.9  [0603]  (hidden comment: CRCW060351R1FKEA)
R51  ValueDisplayed: 100  [0603]  (hidden comment: CRCW06030000Z0EA)
R52  ValueDisplayed: 0.005  [CRE2512-R5_R9]  (hidden comment: CRE2512-FZ-R005E-3)
R53  ValueDisplayed: 100  [0603]  (hidden comment: CRCW06030000Z0EA)
R54  ValueDisplayed: 49.9  [0603]  (hidden comment: CRCW060351R1FKEA)
R55  ValueDisplayed: 5.11  [1206]  (hidden comment: CRCW12066R04FKEA)
R56  ValueDisplayed: 100  [0603]  (hidden comment: CRCW06030000Z0EA)
R57  ValueDisplayed: 12.0  [1206]  (hidden comment: RC1206FR-0712RL)
R58  ValueDisplayed: 20k  [0603]  (hidden comment: CRCW060320K0FKEA)
R59  value 3.3  [1206]  (hidden comment: CRCW12063R30JNEA)
R60  ValueDisplayed: 12.0  [1206]  (hidden comment: RC1206FR-0712RL)
R61  ValueDisplayed: 2.2  [1206]  (hidden comment: RC0603FR-075R11L)
R62  ValueDisplayed: 5.11  [1206]  (hidden comment: CRCW12066R04FKEA)
R63  ValueDisplayed: 10.0k  [0603]  (hidden comment: CRCW060310K0FKEA)
R64  ValueDisplayed: 20k  [0603]  (hidden comment: CRCW060320K0FKEA)
R65  ValueDisplayed: 49.9  [0603]  (hidden comment: CRCW060351R1FKEA)
R66  ValueDisplayed: 100  [0603]  (hidden comment: CRCW0603100RFKEA)
R67  ValueDisplayed: 1.91k  [0603]  (hidden comment: CRCW06031K00FKEA)
R68  ValueDisplayed: 100  [0603]  (hidden comment: CRCW0603100RFKEA)
R69  ValueDisplayed: 1.91k  [0603]  (hidden comment: CRCW06031K00FKEA)
R70  ValueDisplayed: 100  [0603]  (hidden comment: CRCW0603100RFKEA)
R71  ValueDisplayed: 49.9  [0603]  (hidden comment: CRCW060351R1FKEA)
R72  ValueDisplayed: 5.11  [1206]  (hidden comment: CRCW12066R04FKEA)
R73  ValueDisplayed: 2.55k  [0603]  (hidden comment: CRCW06031K00FKEA)
R74  ValueDisplayed: 100  [0603]  (hidden comment: CRCW0603100RFKEA)
R75  ValueDisplayed: 12.0  [1206]  (hidden comment: RC1206FR-0712RL)
R76  ValueDisplayed: 20k  [0603]  (hidden comment: CRCW060320K0FKEA)
R77  ValueDisplayed: 2.55k  [0603]  (hidden comment: CRCW06031K00FKEA)
R112  ValueDisplayed: 10k  [0603]  (hidden comment: CRCW060351R1FKEA)
R113  ValueDisplayed: 10k  [0603]  (hidden comment: CRCW060351R1FKEA)
R114  ValueDisplayed: 10k  [0603]  (hidden comment: CRCW060351R1FKEA)
R115  ValueDisplayed: 10k  [0603]  (hidden comment: CRCW060351R1FKEA)
R116  ValueDisplayed: 10k  [0603]  (hidden comment: CRCW060351R1FKEA)
R117  ValueDisplayed: 10k  [0603]  (hidden comment: CRCW060351R1FKEA)
RT1  MF52-103  value 10k ohm  [NTCALUG03]
U4  UCC27712DR  [D0008B_HV]
U5  UCC27712DR  [D0008B_HV]
U6  UCC27712DR  [D0008B_HV]
U7  TLV9001IDBV  [DBV0005A_N]

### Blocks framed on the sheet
IGBT Temperature Sensing Signal Conditioning: C39 C43 C44 R63 R66-R70 R73 R74 R77 RT1 U7

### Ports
+VDC (out), A_BOT (out), A_TOP (out), B_BOT (out), B_TOP (out), C_BOT (out), C_TOP (out), IA_N (out), IA_P (out), IB_N (out), IB_P (out), IC_N (out), IC_P (out), PHASE_A (out), PHASE_B (out), PHASE_C (out), PWM_A_BOT (out), PWM_A_TOP (out), PWM_B_BOT (out), PWM_B_TOP (out), PWM_C_BOT (out), PWM_C_TOP (out), TEMP_SENSE (in)

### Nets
+3.3VD: C39.1 R63.1 U7.5(V+)
AGND: C23.1 C24.2 C25.2 C26.2 C29.2 C30.2 C31.2 C32.1 C35.2 C36.2 C37.2 C38.1 C39.2 C42.2 C44.1 C45.2 C46.2 C65.1 C66.1 C67.1 R39.1 R44.2 R47.1 R48.2 R52.2 R53.2 R56.1 R58.1 R73.2 R74.2 R76.1 R112.2 R113.2 R114.2 R115.2 R116.2 R117.2 U4.4(COM) U5.4(COM) U6.4(COM) U7.2(V-)  [also labelled GND]
VCC_15V: R32.2 R42.2 R61.2
+VDC: C24.1 C25.1 C26.1 Q1.2(C) Q2.2(C) Q3.2(C) ; port +VDC
A_BOT: C46.1 Q4.1(G) R72.2 R75.2 R76.2 ; port A_BOT
A_TOP: C40.1 Q1.1(G) R60.2 R62.2 R64.2 ; port A_TOP
B_BOT: C37.1 Q5.1(G) R55.2 R57.2 R58.2 ; port B_BOT
B_TOP: C33.1 Q2.1(G) R41.2 R45.2 R49.2 ; port B_TOP
C_BOT: C31.1 Q6.1(G) R37.2 R38.2 R39.2 ; port C_BOT
C_TOP: C27.1 Q3.1(G) R31.2 R33.2 R34.2 ; port C_TOP
IA_N: R47.2 ; port IA_N
IA_P: R43.2 ; port IA_P
IB_N: R56.2 ; port IB_N
IB_P: R51.2 ; port IB_P
IC_N: R53.1 ; port IC_N
IC_P: R46.1 ; port IC_P
PHASE_A: C40.2 C41.2 J1.1 J1.2 Q1.3(E) Q4.2(C) R64.1 U6.6(HS) ; port PHASE_A
PHASE_B: C33.2 C34.2 J2.1 J2.2 Q2.3(E) Q5.2(C) R49.1 U5.6(HS) ; port PHASE_B
PHASE_C: C27.2 C28.2 J3.1 J3.2 Q3.3(E) Q6.2(C) R34.1 U4.6(HS) ; port PHASE_C
PWM_A_BOT: R65.1 ; port PWM_A_BOT
PWM_A_TOP: R71.1 ; port PWM_A_TOP
PWM_B_BOT: R50.1 ; port PWM_B_BOT
PWM_B_TOP: R54.1 ; port PWM_B_TOP
PWM_C_BOT: R35.1 ; port PWM_C_BOT
PWM_C_TOP: R36.1 ; port PWM_C_TOP
TEMP_SENSE: C44.2 R68.2 ; port TEMP_SENSE
NetC23_2: C23.2 C65.2 R30.1 R32.1 U4.3(VDD)
NetC28_1: C28.1 D9.1(K) U4.8(HB)
NetC29_1: C29.1 R35.2 R112.1 U4.1(LI)
NetC30_1: C30.1 R36.2 R113.1 U4.2(HI)
NetC32_2: C32.2 C66.2 R40.1 R42.1 U5.3(VDD)
NetC34_1: C34.1 D12.1(K) U5.8(HB)
NetC35_1: C35.1 R50.2 R114.1 U5.1(LI)
NetC36_1: C36.1 R54.2 R115.1 U5.2(HI)
NetC38_2: C38.2 C67.2 R59.1 R61.1 U6.3(VDD)
NetC41_1: C41.1 D15.1(K) U6.8(HB)
NetC42_1: C42.1 R65.2 R116.1 U6.1(LI)
NetC43_1: C43.1 R69.1 R70.2
NetC43_2: C43.2 R66.2 R67.1
NetC45_1: C45.1 R71.2 R117.1 U6.2(HI)
NetD9_2: D9.2(A) R30.2
NetD10_1: D10.1(K) R33.1 U4.7(HO)
NetD10_2: D10.2(A) R31.1
NetD11_1: D11.1(K) R37.1 U4.5(LO)
NetD11_2: D11.2(A) R38.1
NetD12_2: D12.2(A) R40.2
NetD13_1: D13.1(K) R45.1 U5.7(HO)
NetD13_2: D13.2(A) R41.1
NetD14_1: D14.1(K) R55.1 U5.5(LO)
NetD14_2: D14.2(A) R57.1
NetD15_2: D15.2(A) R59.2
NetD16_1: D16.1(K) R62.1 U6.7(HO)
NetD16_2: D16.2(A) R60.1
NetD17_1: D17.1(K) R72.1 U6.5(LO)
NetD17_2: D17.2(A) R75.1
NetQ4_3: Q4.3(E) R43.1 R44.1
NetQ5_3: Q5.3(E) R51.1 R52.1
NetQ6_3: Q6.3(E) R46.2 R48.1
NetR63_2: R63.2 R70.1 RT1.1
NetR66_1: R66.1 R74.1 RT1.2
NetR67_2: R67.2 R77.1 U7.4(IN-)
NetR68_1: R68.1 R77.2 U7.1(OUT)
NetR69_2: R69.2 R73.1 U7.3(IN+)

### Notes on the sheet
- Gate Driver
- Three Phase Inverter Bridge
- (near J1) Motor Winding Connector
- (near R53) Inverter leg current sensing

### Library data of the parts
C23 C32 C38 = C2012X5R1E106K125AB: CAP, CERM, 10 µF, 25 V, +/- 10%, X5R, 0805; Manufacturer: TDK; Polarized: N; CompType: Capacitor; Value: 10uF; U/M: EA; Cap_F: 0.00001; Tolerance_%: 10; Value1: Unknown; VDC_V: 25; Value2: 25V; TaMin_C: -55; TaMax_C: 85; Cap_Case: 0805; SizeArea_mm2: 2.5; SizeAreaWB_mm2: 6.75; SizeX_mm: 2; SizeY_mm: 1.25; SizeZ_mm: 1.45; AEC Category: Q200
C24-C26 = C1812V104KDRACTU: CAP, CERM, 0.1 µF, 1000 V, +/- 10%, X7R, 1812; Manufacturer: Kemet; Polarized: N; CompType: Capacitor; Value: 0.1uF; U/M: EA; Cap_F: 0.0000001; Tolerance_%: 10; Value1: Unknown; VDC_V: 1000; Value2: 1000V; TaMin_C: -55; TaMax_C: 125; Cap_Case: 1812; SizeArea_mm2: 14.4; SizeAreaWB_mm2: 23.1; SizeX_mm: 4.5; SizeY_mm: 3.2; SizeZ_mm: 2.54; AEC Category: Q200
C27 C31 C33 C37 C40 C46 = GRM188R71E222KA01D: CAP, CERM, 2200 pF, 25 V, +/- 10%, X7R, 0603; Manufacturer: MuRata; Polarized: N; CompType: Capacitor; Value: 2200pF; U/M: EA; Cap_F: 0.0000000022; Tolerance_%: 10; Value1: Unknown; VDC_V: 25; Value2: 25V; TaMin_C: -55; TaMax_C: 125
C28 C34 C41 C65-C67 = C0805C684K5RACTU: CAP, CERM, 0.68 µF, 50 V,+/- 10%, X7R, 0805; Manufacturer: Kemet; Polarized: N; CompType: Capacitor; Value: 0.68uF; U/M: EA; Cap_F: 0.00000068; Tolerance_%: 10; VDC_V: 50; Value2: 50V; TaMin_C: -55; TaMax_C: 125; Cap_Case: 0805; SizeArea_mm2: 2.5; SizeAreaWB_mm2: 6.75; SizeX_mm: 2; SizeY_mm: 1.25; SizeZ_mm: 1.45; AEC Category: Q200; Green_Lifecycle: Active; Green_REACh: Passed
C29 C30 C35 C36 C42 C45 = CGA3E2NP01H330J080AA: CAP, CERM, 33 pF, 50 V,+/- 5%, C0G/NP0, AEC-Q200 Grade 0, 0603; Manufacturer: TDK; Polarized: N; CompType: Capacitor; Value: 33pF; U/M: EA; Cap_F: 0.000000000033; Tolerance_%: 5; VDC_V: 50; Value2: 50V; TaMin_C: -55; TaMax_C: 150; SizeArea_mm2: 1.28; SizeAreaWB_mm2: 4.68; SizeX_mm: 1.6; SizeY_mm: 0.8; SizeZ_mm: 1; AEC Category: Q200; AEC Qualified: Y; AEC Grade: 0; Green_Lifecycle: Active; Green_REACh: Passed
C39 C44 = 0603YC104JAT2A: as C2 on sheet TIDA-010023_Current_Sensing
C43 = 0603YC104JAT2A: as C1 on sheet TIDA-010023_Current_Sensing
D9 D12 D15 = US1M-13-F: Diode, Ultrafast, 1000V, 1A, SMA; Manufacturer: Diodes Inc.; U/M: EA; Vf_V: 1.7; Value2: 1.7V; Io_A: 1; Vr_V: 1000; TJmax_C: 150; RJC_CperW: 30
D10 D11 D13 D14 D16 D17 = 1N5819HW-7-F: as D1 on sheet TIDA-010023_Current_Sensing
J1-J3 = B2P-VH(LF)(SN): Header, 3.96 mm, 2x1, Tin, TH; Manufacturer: JST Manufacturing; SymbolCreator: a0412235; Green_Lifecycle: Active; Green_REACh: Passed
Q1-Q6 = IXYP15N65C3D1, IXYS: Transistor, IGBT, 650 V, 38 A, TO-220AB; Manufacturer: IXYS; SymbolCreator: Altium; PNP: 0; Vceo_V: 650; Vcesat1_V: 2.5; Value: 650 V; IcRated_A: 38; Value1: 38 A; TaMin_C: -55; TaMax_C: 175; SizeAreaWB_mm2: 79.3; SizeArea_mm2: 45.9; SizeX_mm: 10.2; SizeY_mm: 4.5; SizeZ_mm: 19.4; U/M: EA; AEC Category: Q101; AEC Qualified: N
R30 R40 R59 = CRCW12063R30JNEA: RES, 3.3 ohm, 5%, 0.25W, 1206; Manufacturer: Vishay-Dale; CompType: Resistor; Value_Code: 3R30; Tolerance_%: 5; Power_W: 0.25; VDC_V: 200; TempCo: 200 ppm/C; EIA_Code: E24; U/M: EA
R31 R38 R41 R57 R60 R75 = RC1206FR-0712RL: RES, 12.0, 1%, 0.25 W, 1206; Manufacturer: Yageo America; CompType: Resistor; Value: 12.0; Res_ohm: 12; Value_Code: 12R0; Tolerance_%: 1; Power_W: 0.25; Value2: 0.25W; VDC_V: 200; TempCo: 100 ppm/C; SizeArea_mm2: 5.12; SizeX_mm: 3.2; SizeY_mm: 1.6; SizeZ_mm: 1.35; U/M: EA; AEC Category: Q200
R32 R42 R61 = CRM1206-JW-2R2ELF: RES, 2.2, 5%, 0.5 W, 1206; Manufacturer: Bourns; CompType: Resistor; Value: 2.2; Value_Code: 2R20; Tolerance_%: 5; Power_W: 0.5; Value2: 0.5W; VDC_V: 1; TempCo: 100 ppm/C; SizeArea_mm2: 5.12; SizeX_mm: 3.2; SizeY_mm: 1.6; SizeZ_mm: 1.35; EIA_Code: E24; U/M: EA; AEC Category: Q200
R33 R37 R45 R55 R62 R72 = CRCW12065R11FKEA: RES, 5.11, 1%, 0.25 W, 1206; Manufacturer: Vishay-Dale; CompType: Resistor; Value: 5.11; Value_Code: 5R11; Tolerance_%: 1; Power_W: 0.25; Value2: 0.25W; VDC_V: 200; TempCo: 100 ppm/C; SizeArea_mm2: 5.12; SizeX_mm: 3.2; SizeY_mm: 1.6; SizeZ_mm: 1.35; EIA_Code: E96; U/M: EA; AEC Category: Q200
R34 R39 R49 R58 R64 R76 = CRCW060320K0JNEA: RES, 20 k, 5%, 0.1 W, 0603; Manufacturer: Vishay-Dale; CompType: Resistor; Value: 20k; Res_ohm: 20000; Value_Code: 20k0; Tolerance_%: 5; Power_W: 0.1; Value2: 0.1W; VDC_V: 75; TempCo: 200 ppm/C; SizeArea_mm2: 1.28; SizeX_mm: 1.6; SizeY_mm: 0.8; SizeZ_mm: 1; EIA_Code: E24; U/M: EA; AEC Category: Q200; Green_Lifecycle: Active; Green_REACh: Passed
R35 R36 R50 R54 R65 R71 = CRCW060349R9FKEA: RES, 49.9, 1%, 0.1 W, 0603; Manufacturer: Vishay-Dale; CompType: Resistor; Value: 49.9; Value_Code: 49R9; Tolerance_%: 1; Power_W: 0.1; Value2: 0.1W; VDC_V: 75; TempCo: 100 ppm/C; SizeArea_mm2: 1.28; SizeX_mm: 1.6; SizeY_mm: 0.8; EIA_Code: E96; U/M: EA; AEC Category: Q200; Green_Lifecycle: Active; Green_REACh: Passed
R43 R46 R47 R51 R53 R56 = CRCW0603100RFKEA: RES, 100, 1%, 0.1 W, 0603; Manufacturer: Vishay-Dale; CompType: Resistor; Value: 100; Value_Code: 100R; Tolerance_%: 1; Power_W: 0.1; Value2: 0.1W; VDC_V: 75; TempCo: 100 ppm/C; SizeArea_mm2: 1.28; SizeX_mm: 1.6; SizeY_mm: 0.8; EIA_Code: E96; U/M: EA; AEC Category: Q200; Green_Lifecycle: Active; Green_REACh: Passed
R44 R48 R52 = CRE2512-FZ-R005E-3: RES, 0.005, 1%, 3 W, AEC-Q200 Grade 0, 2512; Manufacturer: Bourns; CompType: Resistor; Value: 0.005; Value_Code: 5L000; Tolerance_%: 1; Power_W: 3; Value2: 3W; TempCo: 75 ppm/C; EIA_Code: E96; U/M: EA; SizeArea_mm2: 21.6075; SizeX_mm: 6.45; SizeY_mm: 3.35; SizeZ_mm: 0.9; AEC Category: Q200; AEC Qualified: Y; AEC Grade: 0
R63 = CRCW060310K0FKEA: RES, 10.0 k, 1%, 0.1 W, 0603; Manufacturer: Vishay-Dale; CompType: Resistor; Value: 10.0k; Res_ohm: 10000; Value_Code: 10k0; Tolerance_%: 1; Power_W: 0.1; Value2: 0.1W; VDC_V: 75; TempCo: 100 ppm/C; SizeArea_mm2: 1.28; SizeX_mm: 1.6; SizeY_mm: 0.8; EIA_Code: E96; U/M: EA; AEC Category: Q200
R66 R68 R70 R74 = CRCW0603100RFKEA: RES, 100, 1%, 0.1 W, 0603; Manufacturer: Vishay-Dale; CompType: Resistor; Value: 100; Value_Code: 100R; Tolerance_%: 1; Power_W: 0.1; Value2: 0.1W; VDC_V: 75; TempCo: 100 ppm/C; EIA_Code: E96; U/M: EA; SizeArea_mm2: 1.28; SizeX_mm: 1.6; SizeY_mm: 0.8; AEC Category: Q200
R67 R69 = CRCW06031K91FKEA: as R1 on sheet TIDA-010023_Current_Sensing
R73 R77 = CRCW06032K55FKEA: RES, 2.55 k, 1%, 0.1 W, 0603; Manufacturer: Vishay-Dale; CompType: Resistor; Value: 2.55k; Res_ohm: 2550; Value_Code: 2k55; Tolerance_%: 1; Power_W: 0.1; Value2: 0.1W; VDC_V: 75; TempCo: 100 ppm/C; SizeArea_mm2: 1.28; SizeX_mm: 1.6; SizeY_mm: 0.8; EIA_Code: E96; U/M: EA; AEC Category: Q200; Green_Lifecycle: Active; Green_REACh: Passed
R112-R117 = CRCW060310K0JNEA: as R12 on sheet TIDA-010023_Current_Sensing
RT1 = NTCALUG03A103G: Thermistor NTC, 10k ohm, 2%, NTC Thermistor, Mini Lug Sensor, Pitch 1.5mm; Manufacturer: Vishay-Bccomponents; Tolerance_%: 2; Power_W: 0.1; TaMin_C: -40; TaMax_C: 125; U/M: EA
U4-U6 = UCC27712DR: 620-V High-Side Low-Side Gate Driver with 2.5A Peak Output and RobustDrive, D0008B (SOIC-8); Manufacturer: Texas Instruments; SymbolCreator: a0411947; SizeArea_mm2: 29.4; SizeAreaWB_mm2: 55.2; SizeX_mm: 6; SizeY_mm: 4.9; SizeZ_mm: 1.75; CompType: IC; U/M: EA
U7 = LMV721IDBV: 1-MHz, Low-Power Operational Amplifier; PartNumber: TLV6001IDBVT; Manufacturer: Texas Instruments; CompType: OpAmp IC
